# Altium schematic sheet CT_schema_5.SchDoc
size 145 x 123 mm
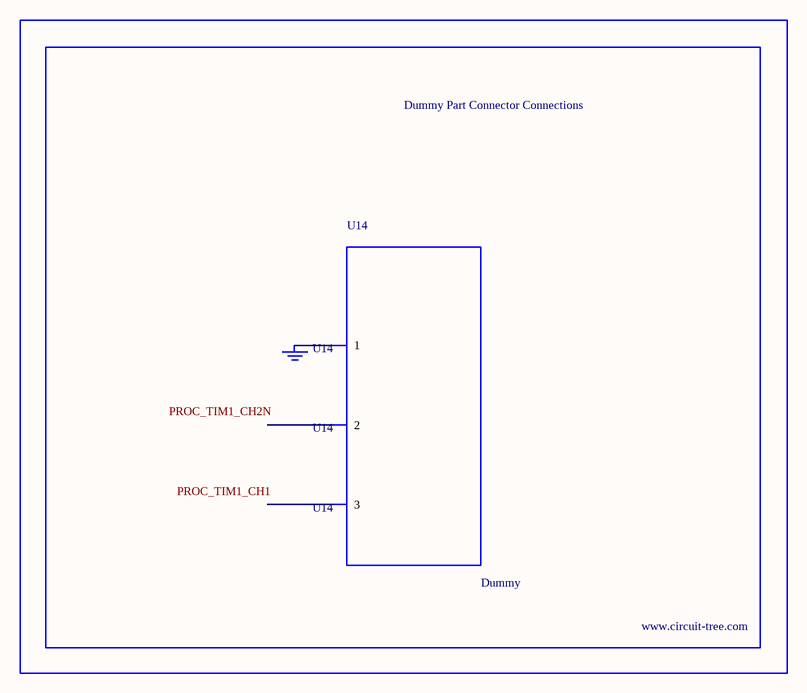
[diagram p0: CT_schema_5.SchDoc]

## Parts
BORDER4  (no value)
GND_INSTANCE_4_0  (no value)
U14  Dummy  [DUMMY_PACKAGE_132]

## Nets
NetGND_INSTANCE_4_0_0: GND_INSTANCE_4_0.0(GND) U14.1

Not connected (* = marked no-connect by the designer): U14 2 3

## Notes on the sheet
- Labels drawn without touching a wire or pin: PROC_TIM1_CH1, PROC_TIM1_CH2N

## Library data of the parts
BORDER4 = BORDER_PAGE4
GND_INSTANCE_4_0 = GND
